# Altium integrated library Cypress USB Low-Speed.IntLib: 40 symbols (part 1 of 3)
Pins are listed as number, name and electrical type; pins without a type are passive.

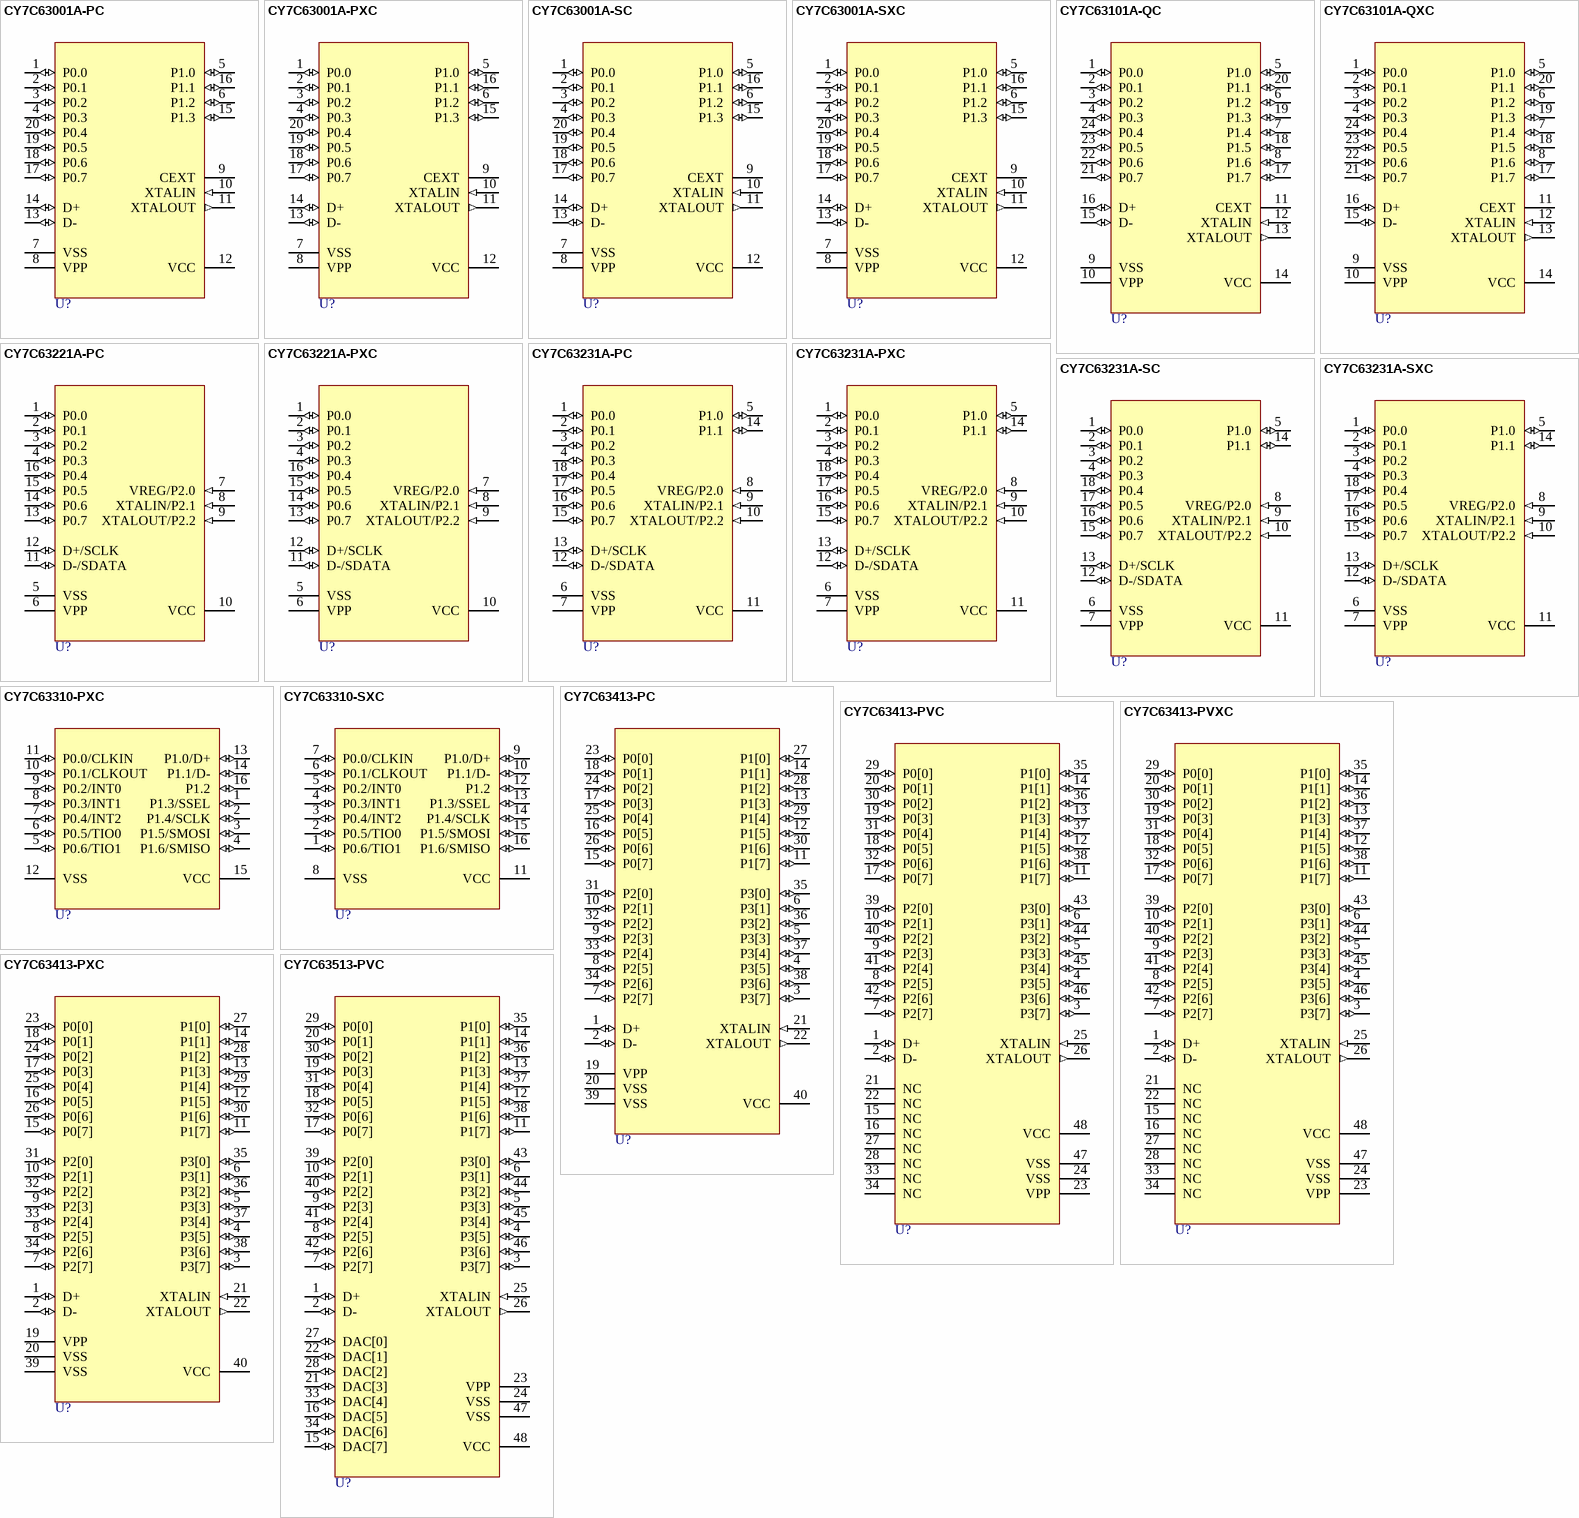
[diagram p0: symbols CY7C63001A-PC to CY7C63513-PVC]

## CY7C63001A-PC
designator U?
Low-Speed USB Peripheral Controller, 4KB EPROM, 20-Pin PDIP, Commercial Grade
footprint P5 (DIP, 20-Leads, Row Spacing 7.62mm, Pitch 2.54mm, Body 25.53x6.6mm)
pins: 1 P0.0 (io) "Port 0 bit 0", 2 P0.1 (io) "Port 0 bit 1", 3 P0.2 (io) "Port 0 bit 2", 4 P0.3 (io) "Port 0 bit 3", 5 P1.0 (io) "Port 1 bit 0", 6 P1.2 (io) "Port 1 bit 2", 7 VSS (power) "Ground", 8 VPP (power) "Programming voltage supply, tie to ground during normal operation", 9 CEXT "Connects to external R/C timing circuit for optional ‘suspend’ wakeup", 10 XTALIN (in) "Ceramic resonator", 11 XTALOUT (out) "Ceramic resonator out", 12 VCC (power) "Voltage supply", 13 D- (io) "USB data-", 14 D+ (io) "USB data+", 15 P1.3 (io) "Port 1 bit 3", 16 P1.1 (io) "Port 1 bit 1", 17 P0.7 (io) "Port 0 bit 7", 18 P0.6 (io) "Port 0 bit 6", 19 P0.5 (io) "Port 0 bit 5", 20 P0.4 (io) "Port 0 bit 4"

## CY7C63001A-PXC
designator U?
Low-Speed USB Peripheral Controller, 4KB EPROM, 20-Pin PDIP, Commercial Grade, Pb-free
footprint P5 (DIP, 20-Leads, Row Spacing 7.62mm, Pitch 2.54mm, Body 25.53x6.6mm)
pins: 1 P0.0 (io) "Port 0 bit 0", 2 P0.1 (io) "Port 0 bit 1", 3 P0.2 (io) "Port 0 bit 2", 4 P0.3 (io) "Port 0 bit 3", 5 P1.0 (io) "Port 1 bit 0", 6 P1.2 (io) "Port 1 bit 2", 7 VSS (power) "Ground", 8 VPP (power) "Programming voltage supply, tie to ground during normal operation", 9 CEXT "Connects to external R/C timing circuit for optional ‘suspend’ wakeup", 10 XTALIN (in) "Ceramic resonator", 11 XTALOUT (out) "Ceramic resonator out", 12 VCC (power) "Voltage supply", 13 D- (io) "USB data-", 14 D+ (io) "USB data+", 15 P1.3 (io) "Port 1 bit 3", 16 P1.1 (io) "Port 1 bit 1", 17 P0.7 (io) "Port 0 bit 7", 18 P0.6 (io) "Port 0 bit 6", 19 P0.5 (io) "Port 0 bit 5", 20 P0.4 (io) "Port 0 bit 4"

## CY7C63001A-SC
designator U?
Low-Speed USB Peripheral Controller, 4KB EPROM, 20-Pin SOIC, Commercial Grade
footprint S5_N (SOIC, 20-Leads, Body 12.8x7.5mm, Pitch 1.27mm, IPC Medium Density)
footprint S5_L (SOIC, 20-Leads, Body 12.8x7.5mm, Pitch 1.27mm, IPC High Density)
footprint S5_M (SOIC, 20-Leads, Body 12.8x7.5mm, Pitch 1.27mm, IPC Low Density)
pins: 1 P0.0 (io) "Port 0 bit 0", 2 P0.1 (io) "Port 0 bit 1", 3 P0.2 (io) "Port 0 bit 2", 4 P0.3 (io) "Port 0 bit 3", 5 P1.0 (io) "Port 1 bit 0", 6 P1.2 (io) "Port 1 bit 2", 7 VSS (power) "Ground", 8 VPP (power) "Programming voltage supply, tie to ground during normal operation", 9 CEXT "Connects to external R/C timing circuit for optional ‘suspend’ wakeup", 10 XTALIN (in) "Ceramic resonator", 11 XTALOUT (out) "Ceramic resonator out", 12 VCC (power) "Voltage supply", 13 D- (io) "USB data-", 14 D+ (io) "USB data+", 15 P1.3 (io) "Port 1 bit 3", 16 P1.1 (io) "Port 1 bit 1", 17 P0.7 (io) "Port 0 bit 7", 18 P0.6 (io) "Port 0 bit 6", 19 P0.5 (io) "Port 0 bit 5", 20 P0.4 (io) "Port 0 bit 4"

## CY7C63001A-SXC
designator U?
Low-Speed USB Peripheral Controller, 4KB EPROM, 20-Pin SOIC, Commercial Grade, Pb-free
footprint S5_N (SOIC, 20-Leads, Body 12.8x7.5mm, Pitch 1.27mm, IPC Medium Density)
footprint S5_L (SOIC, 20-Leads, Body 12.8x7.5mm, Pitch 1.27mm, IPC High Density)
footprint S5_M (SOIC, 20-Leads, Body 12.8x7.5mm, Pitch 1.27mm, IPC Low Density)
pins: 1 P0.0 (io) "Port 0 bit 0", 2 P0.1 (io) "Port 0 bit 1", 3 P0.2 (io) "Port 0 bit 2", 4 P0.3 (io) "Port 0 bit 3", 5 P1.0 (io) "Port 1 bit 0", 6 P1.2 (io) "Port 1 bit 2", 7 VSS (power) "Ground", 8 VPP (power) "Programming voltage supply, tie to ground during normal operation", 9 CEXT "Connects to external R/C timing circuit for optional ‘suspend’ wakeup", 10 XTALIN (in) "Ceramic resonator", 11 XTALOUT (out) "Ceramic resonator out", 12 VCC (power) "Voltage supply", 13 D- (io) "USB data-", 14 D+ (io) "USB data+", 15 P1.3 (io) "Port 1 bit 3", 16 P1.1 (io) "Port 1 bit 1", 17 P0.7 (io) "Port 0 bit 7", 18 P0.6 (io) "Port 0 bit 6", 19 P0.5 (io) "Port 0 bit 5", 20 P0.4 (io) "Port 0 bit 4"

## CY7C63101A-QC
designator U?
Low-Speed USB Peripheral Controller, 4KB EPROM, 24-Pin QSOP, Commercial Grade
footprint Q13_N (SOP, 24-Leads, Body 8.6x3.9mm, Pitch 0.635mm, IPC Medium Density)
footprint Q13_L (SOP, 24-Leads, Body 8.6x3.9mm, Pitch 0.635mm, IPC High Density)
footprint Q13_M (SOP, 24-Leads, Body 8.6x3.9mm, Pitch 0.635mm, IPC Low Density)
pins: 1 P0.0 (io) "Port 0 bit 0", 2 P0.1 (io) "Port 0 bit 1", 3 P0.2 (io) "Port 0 bit 2", 4 P0.3 (io) "Port 0 bit 3", 5 P1.0 (io) "Port 1 bit 0", 6 P1.2 (io) "Port 1 bit 2", 7 P1.4 (io) "Port 1 bit 4", 8 P1.6 (io) "Port 1 bit 6", 9 VSS (power) "Ground", 10 VPP (power) "Programming voltage supply, tie to ground during normal operation", 11 CEXT "Connects to external R/C timing circuit for optional ‘suspend’ wakeup", 12 XTALIN (in) "Ceramic resonator", 13 XTALOUT (out) "Ceramic resonator out", 14 VCC (power) "Voltage supply", 15 D- (io) "USB data-", 16 D+ (io) "USB data+", 17 P1.7 (io) "Port 1 bit 7", 18 P1.5 (io) "Port 1 bit 5", 19 P1.3 (io) "Port 1 bit 3", 20 P1.1 (io) "Port 1 bit 1", 21 P0.7 (io) "Port 0 bit 7", 22 P0.6 (io) "Port 0 bit 6", 23 P0.5 (io) "Port 0 bit 5", 24 P0.4 (io) "Port 0 bit 4"

## CY7C63101A-QXC
designator U?
Low-Speed USB Peripheral Controller, 4KB EPROM, 24-Pin QSOP, Commercial Grade, Pb-free
footprint Q13_N (SOP, 24-Leads, Body 8.6x3.9mm, Pitch 0.635mm, IPC Medium Density)
footprint Q13_L (SOP, 24-Leads, Body 8.6x3.9mm, Pitch 0.635mm, IPC High Density)
footprint Q13_M (SOP, 24-Leads, Body 8.6x3.9mm, Pitch 0.635mm, IPC Low Density)
pins: 1 P0.0 (io) "Port 0 bit 0", 2 P0.1 (io) "Port 0 bit 1", 3 P0.2 (io) "Port 0 bit 2", 4 P0.3 (io) "Port 0 bit 3", 5 P1.0 (io) "Port 1 bit 0", 6 P1.2 (io) "Port 1 bit 2", 7 P1.4 (io) "Port 1 bit 4", 8 P1.6 (io) "Port 1 bit 6", 9 VSS (power) "Ground", 10 VPP (power) "Programming voltage supply, tie to ground during normal operation", 11 CEXT "Connects to external R/C timing circuit for optional ‘suspend’ wakeup", 12 XTALIN (in) "Ceramic resonator", 13 XTALOUT (out) "Ceramic resonator out", 14 VCC (power) "Voltage supply", 15 D- (io) "USB data-", 16 D+ (io) "USB data+", 17 P1.7 (io) "Port 1 bit 7", 18 P1.5 (io) "Port 1 bit 5", 19 P1.3 (io) "Port 1 bit 3", 20 P1.1 (io) "Port 1 bit 1", 21 P0.7 (io) "Port 0 bit 7", 22 P0.6 (io) "Port 0 bit 6", 23 P0.5 (io) "Port 0 bit 5", 24 P0.4 (io) "Port 0 bit 4"

## CY7C63221A-PC
designator U?
enCoRe, Low-Speed USB Peripheral Controller, 3KB EPROM, 16-Pin PDIP, Commercial Grade
footprint P1 (DIP, 16-Leads, Row Spacing 7.62mm, Pitch 2.54mm, Body 19.18x6.35mm)
pins: 1 P0.0 (io) "GPIO Port 0 capable of sinking up to 50 mA/pin, or sinking controlled low or high programmable current. Can also source 2 mA current, provide a resistive pull-up, or serve as a high-impedance input.", 2 P0.1 (io) "GPIO Port 0 capable of sinking up to 50 mA/pin, or sinking controlled low or high programmable current. Can also source 2 mA current, provide a resistive pull-up, or serve as a high-impedance input.", 3 P0.2 (io) "GPIO Port 0 capable of sinking up to 50 mA/pin, or sinking controlled low or high programmable current. Can also source 2 mA current, provide a resistive pull-up, or serve as a high-impedance input.", 4 P0.3 (io) "GPIO Port 0 capable of sinking up to 50 mA/pin, or sinking controlled low or high programmable current. Can also source 2 mA current, provide a resistive pull-up, or serve as a high-impedance input.", 5 VSS (power) "Ground", 6 VPP (power) "Programming voltage supply, ground for normal operation", 7 VREG/P2.0 (in) "Voltage supply for 1.3-k? USB pull-up resistor (3.3V nominal). Also serves as P2.0 input.", 8 XTALIN/P2.1 (in) "6-MHz ceramic resonator or external clock input, or P2.1 input", 9 XTALOUT/P2.2 (in) "6-MHz ceramic resonator return pin or internal oscillator output, or P2.2 input", 10 VCC (power) "Voltage supply", 11 D-/SDATA (io) "USB differential data line or PS/2 data signal", 12 D+/SCLK (io) "USB differential data line or PS/2 clock signal", 13 P0.7 (io) "GPIO Port 0 capable of sinking up to 50 mA/pin, or sinking controlled low or high programmable current. Can also source 2 mA current, provide a resistive pull-up, or serve as a high-impedance input.", 14 P0.6 (io) "GPIO Port 0 capable of sinking up to 50 mA/pin, or sinking controlled low or high programmable current. Can also source 2 mA current, provide a resistive pull-up, or serve as a high-impedance input.", 15 P0.5 (io) "GPIO Port 0 capable of sinking up to 50 mA/pin, or sinking controlled low or high programmable current. Can also source 2 mA current, provide a resistive pull-up, or serve as a high-impedance input.", 16 P0.4 (io) "GPIO Port 0 capable of sinking up to 50 mA/pin, or sinking controlled low or high programmable current. Can also source 2 mA current, provide a resistive pull-up, or serve as a high-impedance input."

## CY7C63221A-PXC
designator U?
enCoRe, Low-Speed USB Peripheral Controller, 3KB EPROM, 16-Pin PDIP, Commercial Grade, Pb-free
footprint P1 (DIP, 16-Leads, Row Spacing 7.62mm, Pitch 2.54mm, Body 19.18x6.35mm)
pins: 1 P0.0 (io) "GPIO Port 0 capable of sinking up to 50 mA/pin, or sinking controlled low or high programmable current. Can also source 2 mA current, provide a resistive pull-up, or serve as a high-impedance input.", 2 P0.1 (io) "GPIO Port 0 capable of sinking up to 50 mA/pin, or sinking controlled low or high programmable current. Can also source 2 mA current, provide a resistive pull-up, or serve as a high-impedance input.", 3 P0.2 (io) "GPIO Port 0 capable of sinking up to 50 mA/pin, or sinking controlled low or high programmable current. Can also source 2 mA current, provide a resistive pull-up, or serve as a high-impedance input.", 4 P0.3 (io) "GPIO Port 0 capable of sinking up to 50 mA/pin, or sinking controlled low or high programmable current. Can also source 2 mA current, provide a resistive pull-up, or serve as a high-impedance input.", 5 VSS (power) "Ground", 6 VPP (power) "Programming voltage supply, ground for normal operation", 7 VREG/P2.0 (in) "Voltage supply for 1.3-k? USB pull-up resistor (3.3V nominal). Also serves as P2.0 input.", 8 XTALIN/P2.1 (in) "6-MHz ceramic resonator or external clock input, or P2.1 input", 9 XTALOUT/P2.2 (in) "6-MHz ceramic resonator return pin or internal oscillator output, or P2.2 input", 10 VCC (power) "Voltage supply", 11 D-/SDATA (io) "USB differential data line or PS/2 data signal", 12 D+/SCLK (io) "USB differential data line or PS/2 clock signal", 13 P0.7 (io) "GPIO Port 0 capable of sinking up to 50 mA/pin, or sinking controlled low or high programmable current. Can also source 2 mA current, provide a resistive pull-up, or serve as a high-impedance input.", 14 P0.6 (io) "GPIO Port 0 capable of sinking up to 50 mA/pin, or sinking controlled low or high programmable current. Can also source 2 mA current, provide a resistive pull-up, or serve as a high-impedance input.", 15 P0.5 (io) "GPIO Port 0 capable of sinking up to 50 mA/pin, or sinking controlled low or high programmable current. Can also source 2 mA current, provide a resistive pull-up, or serve as a high-impedance input.", 16 P0.4 (io) "GPIO Port 0 capable of sinking up to 50 mA/pin, or sinking controlled low or high programmable current. Can also source 2 mA current, provide a resistive pull-up, or serve as a high-impedance input."

## CY7C63231A-PC
designator U?
enCoRe, Low-Speed USB Peripheral Controller, 3KB EPROM, 18-Pin PDIP, Commercial Grade
footprint P3 (DIP, 18-Leads, Row Spacing 7.62mm, Pitch 2.54mm, Body 22.73x6.48mm)
pins: 1 P0.0 (io) "GPIO Port 0 capable of sinking up to 50 mA/pin, or sinking controlled low or high programmable current. Can also source 2 mA current, provide a resistive pull-up, or serve as a high-impedance input.", 2 P0.1 (io) "GPIO Port 0 capable of sinking up to 50 mA/pin, or sinking controlled low or high programmable current. Can also source 2 mA current, provide a resistive pull-up, or serve as a high-impedance input.", 3 P0.2 (io) "GPIO Port 0 capable of sinking up to 50 mA/pin, or sinking controlled low or high programmable current. Can also source 2 mA current, provide a resistive pull-up, or serve as a high-impedance input.", 4 P0.3 (io) "GPIO Port 0 capable of sinking up to 50 mA/pin, or sinking controlled low or high programmable current. Can also source 2 mA current, provide a resistive pull-up, or serve as a high-impedance input.", 5 P1.0 (io) "IO Port 1 capable of sinking up to 50 mA/pin, or sinking controlled low or high programmable current. Can also source 2 mA current, provide a resistive pull-up, or serve as a high-impedance input.", 6 VSS (power) "Ground", 7 VPP (power) "Programming voltage supply, ground for normal operation", 8 VREG/P2.0 (in) "Voltage supply for 1.3-k? USB pull-up resistor (3.3V nominal). Also serves as P2.0 input.", 9 XTALIN/P2.1 (in) "6-MHz ceramic resonator or external clock input, or P2.1 input", 10 XTALOUT/P2.2 (in) "6-MHz ceramic resonator return pin or internal oscillator output, or P2.2 input", 11 VCC (power) "Voltage supply", 12 D-/SDATA (io) "USB differential data line or PS/2 data signal", 13 D+/SCLK (io) "USB differential data line or PS/2 clock signal", 14 P1.1 (io) "IO Port 1 capable of sinking up to 50 mA/pin, or sinking controlled low or high programmable current. Can also source 2 mA current, provide a resistive pull-up, or serve as a high-impedance input.", 15 P0.7 (io) "GPIO Port 0 capable of sinking up to 50 mA/pin, or sinking controlled low or high programmable current. Can also source 2 mA current, provide a resistive pull-up, or serve as a high-impedance input.", 16 P0.6 (io) "GPIO Port 0 capable of sinking up to 50 mA/pin, or sinking controlled low or high programmable current. Can also source 2 mA current, provide a resistive pull-up, or serve as a high-impedance input.", 17 P0.5 (io) "GPIO Port 0 capable of sinking up to 50 mA/pin, or sinking controlled low or high programmable current. Can also source 2 mA current, provide a resistive pull-up, or serve as a high-impedance input.", 18 P0.4 (io) "GPIO Port 0 capable of sinking up to 50 mA/pin, or sinking controlled low or high programmable current. Can also source 2 mA current, provide a resistive pull-up, or serve as a high-impedance input."

## CY7C63231A-PXC
designator U?
enCoRe, Low-Speed USB Peripheral Controller, 3KB EPROM, 18-Pin PDIP, Commercial Grade, Pb-free
footprint P3 (DIP, 18-Leads, Row Spacing 7.62mm, Pitch 2.54mm, Body 22.73x6.48mm)
pins: 1 P0.0 (io) "GPIO Port 0 capable of sinking up to 50 mA/pin, or sinking controlled low or high programmable current. Can also source 2 mA current, provide a resistive pull-up, or serve as a high-impedance input.", 2 P0.1 (io) "GPIO Port 0 capable of sinking up to 50 mA/pin, or sinking controlled low or high programmable current. Can also source 2 mA current, provide a resistive pull-up, or serve as a high-impedance input.", 3 P0.2 (io) "GPIO Port 0 capable of sinking up to 50 mA/pin, or sinking controlled low or high programmable current. Can also source 2 mA current, provide a resistive pull-up, or serve as a high-impedance input.", 4 P0.3 (io) "GPIO Port 0 capable of sinking up to 50 mA/pin, or sinking controlled low or high programmable current. Can also source 2 mA current, provide a resistive pull-up, or serve as a high-impedance input.", 5 P1.0 (io) "IO Port 1 capable of sinking up to 50 mA/pin, or sinking controlled low or high programmable current. Can also source 2 mA current, provide a resistive pull-up, or serve as a high-impedance input.", 6 VSS (power) "Ground", 7 VPP (power) "Programming voltage supply, ground for normal operation", 8 VREG/P2.0 (in) "Voltage supply for 1.3-k? USB pull-up resistor (3.3V nominal). Also serves as P2.0 input.", 9 XTALIN/P2.1 (in) "6-MHz ceramic resonator or external clock input, or P2.1 input", 10 XTALOUT/P2.2 (in) "6-MHz ceramic resonator return pin or internal oscillator output, or P2.2 input", 11 VCC (power) "Voltage supply", 12 D-/SDATA (io) "USB differential data line or PS/2 data signal", 13 D+/SCLK (io) "USB differential data line or PS/2 clock signal", 14 P1.1 (io) "IO Port 1 capable of sinking up to 50 mA/pin, or sinking controlled low or high programmable current. Can also source 2 mA current, provide a resistive pull-up, or serve as a high-impedance input.", 15 P0.7 (io) "GPIO Port 0 capable of sinking up to 50 mA/pin, or sinking controlled low or high programmable current. Can also source 2 mA current, provide a resistive pull-up, or serve as a high-impedance input.", 16 P0.6 (io) "GPIO Port 0 capable of sinking up to 50 mA/pin, or sinking controlled low or high programmable current. Can also source 2 mA current, provide a resistive pull-up, or serve as a high-impedance input.", 17 P0.5 (io) "GPIO Port 0 capable of sinking up to 50 mA/pin, or sinking controlled low or high programmable current. Can also source 2 mA current, provide a resistive pull-up, or serve as a high-impedance input.", 18 P0.4 (io) "GPIO Port 0 capable of sinking up to 50 mA/pin, or sinking controlled low or high programmable current. Can also source 2 mA current, provide a resistive pull-up, or serve as a high-impedance input."

## CY7C63231A-SC
designator U?
enCoRe, Low-Speed USB Peripheral Controller, 3KB EPROM, 18-Pin SOIC, Commercial Grade
footprint S1_N (SOIC, 18-Leads, Body 11.6x7.5mm, Pitch 1.27mm, IPC Medium Density)
footprint S1_L (SOIC, 18-Leads, Body 11.6x7.5mm, Pitch 1.27mm, IPC High Density)
footprint S1_M (SOIC, 18-Leads, Body 11.6x7.5mm, Pitch 1.27mm, IPC Low Density)
pins: 1 P0.0 (io) "GPIO Port 0 capable of sinking up to 50 mA/pin, or sinking controlled low or high programmable current. Can also source 2 mA current, provide a resistive pull-up, or serve as a high-impedance input.", 2 P0.1 (io) "GPIO Port 0 capable of sinking up to 50 mA/pin, or sinking controlled low or high programmable current. Can also source 2 mA current, provide a resistive pull-up, or serve as a high-impedance input.", 3 P0.2 (io) "GPIO Port 0 capable of sinking up to 50 mA/pin, or sinking controlled low or high programmable current. Can also source 2 mA current, provide a resistive pull-up, or serve as a high-impedance input.", 4 P0.3 (io) "GPIO Port 0 capable of sinking up to 50 mA/pin, or sinking controlled low or high programmable current. Can also source 2 mA current, provide a resistive pull-up, or serve as a high-impedance input.", 5 P1.0 (io) "IO Port 1 capable of sinking up to 50 mA/pin, or sinking controlled low or high programmable current. Can also source 2 mA current, provide a resistive pull-up, or serve as a high-impedance input.", 6 VSS (power) "Ground", 7 VPP (power) "Programming voltage supply, ground for normal operation", 8 VREG/P2.0 (in) "Voltage supply for 1.3-k? USB pull-up resistor (3.3V nominal). Also serves as P2.0 input.", 9 XTALIN/P2.1 (in) "6-MHz ceramic resonator or external clock input, or P2.1 input", 10 XTALOUT/P2.2 (in) "6-MHz ceramic resonator return pin or internal oscillator output, or P2.2 input", 11 VCC (power) "Voltage supply", 12 D-/SDATA (io) "USB differential data line or PS/2 data signal", 13 D+/SCLK (io) "USB differential data line or PS/2 clock signal", 14 P1.1 (io) "IO Port 1 capable of sinking up to 50 mA/pin, or sinking controlled low or high programmable current. Can also source 2 mA current, provide a resistive pull-up, or serve as a high-impedance input.", 15 P0.7 (io) "GPIO Port 0 capable of sinking up to 50 mA/pin, or sinking controlled low or high programmable current. Can also source 2 mA current, provide a resistive pull-up, or serve as a high-impedance input.", 16 P0.6 (io) "GPIO Port 0 capable of sinking up to 50 mA/pin, or sinking controlled low or high programmable current. Can also source 2 mA current, provide a resistive pull-up, or serve as a high-impedance input.", 17 P0.5 (io) "GPIO Port 0 capable of sinking up to 50 mA/pin, or sinking controlled low or high programmable current. Can also source 2 mA current, provide a resistive pull-up, or serve as a high-impedance input.", 18 P0.4 (io) "GPIO Port 0 capable of sinking up to 50 mA/pin, or sinking controlled low or high programmable current. Can also source 2 mA current, provide a resistive pull-up, or serve as a high-impedance input."

## CY7C63231A-SXC
designator U?
enCoRe, Low-Speed USB Peripheral Controller, 3KB EPROM, 18-Pin SOIC, Commercial Grade, Pb-free
footprint S1_N (SOIC, 18-Leads, Body 11.6x7.5mm, Pitch 1.27mm, IPC Medium Density)
footprint S1_L (SOIC, 18-Leads, Body 11.6x7.5mm, Pitch 1.27mm, IPC High Density)
footprint S1_M (SOIC, 18-Leads, Body 11.6x7.5mm, Pitch 1.27mm, IPC Low Density)
pins: 1 P0.0 (io) "GPIO Port 0 capable of sinking up to 50 mA/pin, or sinking controlled low or high programmable current. Can also source 2 mA current, provide a resistive pull-up, or serve as a high-impedance input.", 2 P0.1 (io) "GPIO Port 0 capable of sinking up to 50 mA/pin, or sinking controlled low or high programmable current. Can also source 2 mA current, provide a resistive pull-up, or serve as a high-impedance input.", 3 P0.2 (io) "GPIO Port 0 capable of sinking up to 50 mA/pin, or sinking controlled low or high programmable current. Can also source 2 mA current, provide a resistive pull-up, or serve as a high-impedance input.", 4 P0.3 (io) "GPIO Port 0 capable of sinking up to 50 mA/pin, or sinking controlled low or high programmable current. Can also source 2 mA current, provide a resistive pull-up, or serve as a high-impedance input.", 5 P1.0 (io) "IO Port 1 capable of sinking up to 50 mA/pin, or sinking controlled low or high programmable current. Can also source 2 mA current, provide a resistive pull-up, or serve as a high-impedance input.", 6 VSS (power) "Ground", 7 VPP (power) "Programming voltage supply, ground for normal operation", 8 VREG/P2.0 (in) "Voltage supply for 1.3-k? USB pull-up resistor (3.3V nominal). Also serves as P2.0 input.", 9 XTALIN/P2.1 (in) "6-MHz ceramic resonator or external clock input, or P2.1 input", 10 XTALOUT/P2.2 (in) "6-MHz ceramic resonator return pin or internal oscillator output, or P2.2 input", 11 VCC (power) "Voltage supply", 12 D-/SDATA (io) "USB differential data line or PS/2 data signal", 13 D+/SCLK (io) "USB differential data line or PS/2 clock signal", 14 P1.1 (io) "IO Port 1 capable of sinking up to 50 mA/pin, or sinking controlled low or high programmable current. Can also source 2 mA current, provide a resistive pull-up, or serve as a high-impedance input.", 15 P0.7 (io) "GPIO Port 0 capable of sinking up to 50 mA/pin, or sinking controlled low or high programmable current. Can also source 2 mA current, provide a resistive pull-up, or serve as a high-impedance input.", 16 P0.6 (io) "GPIO Port 0 capable of sinking up to 50 mA/pin, or sinking controlled low or high programmable current. Can also source 2 mA current, provide a resistive pull-up, or serve as a high-impedance input.", 17 P0.5 (io) "GPIO Port 0 capable of sinking up to 50 mA/pin, or sinking controlled low or high programmable current. Can also source 2 mA current, provide a resistive pull-up, or serve as a high-impedance input.", 18 P0.4 (io) "GPIO Port 0 capable of sinking up to 50 mA/pin, or sinking controlled low or high programmable current. Can also source 2 mA current, provide a resistive pull-up, or serve as a high-impedance input."

## CY7C63310-PXC
designator U?
enCoRe II, Low-Speed USB Peripheral Controller, 3KB FLASH, 16-Pin PDIP, Commercial Grade, Pb-free
footprint P1 (DIP, 16-Leads, Row Spacing 7.62mm, Pitch 2.54mm, Body 19.18x6.35mm)
pins: 1 P1.3/SSEL (io) "GPIO Port 1 bit 3 - Configured individually. Alternate function is SSEL signal of the SPI bus TTL voltage thresholds", 2 P1.4/SCLK (io) "GPIO Port 1 bit 4 - Configured individually. Alternate function is SCLK signal of the SPI bus TTL voltage thresholds", 3 P1.5/SMOSI (io) "GPIO Port 1 bit 5 - Configured individually. Alternate function is SMOSI signal of the SPI bus TTL voltage thresholds", 4 P1.6/SMISO (io) "GPIO Port 1 bit 6 - Configured individually. Alternate function is SMISO signal of the SPI bus TTL voltage thresholds", 5 P0.6/TIO1 (io) "GPIO port 0 bit 6 - Configured individually Alternate function Timer capture inputs or Timer output TIO1", 6 P0.5/TIO0 (io) "GPIO port 0 bit 5 - Configured individually Alternate function Timer capture inputs or Timer output TIO0", 7 P0.4/INT2 (io) "GPIO port 0 bit 4 - Configured individually Optional rising edge interrupt INT2", 8 P0.3/INT1 (io) "GPIO port 0 bit 3 - Configured individually Optional rising edge interrupt INT1", 9 P0.2/INT0 (io) "GPIO port 0 bit 2 - Configured individually Optional rising edge interrupt INT0", 10 P0.1/CLKOUT (io) "GPIO Port 0 bit 1 - Configured individually. Oscillator output when configured as Clock Out.", 11 P0.0/CLKIN (io) "GPIO Port 0 bit 0 - Configured individually. Oscillator input when configured as Clock In.", 12 VSS (power) "Ground", 13 P1.0/D+ (io) "GPIO Port 1 bit 0 / USB D+", 14 P1.1/D- (io) "GPIO Port 1 bit 1 / USB D-", 15 VCC (power) "Power", 16 P1.2 (io) "GPIO Port 1 bit 2 - Configured individually."

## CY7C63310-SXC
designator U?
enCoRe II, Low-Speed USB Peripheral Controller, 3KB FLASH, 16-Pin SOIC, Commercial Grade, Pb-free
footprint S16.15_N (SOIC, 16-Leads, Body 9.9x3.9mm, Pitch 1.27mm, IPC Medium Density)
footprint S16.15_L (SOIC, 16-Leads, Body 9.9x3.9mm, Pitch 1.27mm, IPC High Density)
footprint S16.15_M (SOIC, 16-Leads, Body 9.9x3.9mm, Pitch 1.27mm, IPC Low Density)
pins: 1 P0.6/TIO1 (io) "GPIO port 0 bit 6 - Configured individually Alternate function Timer capture inputs or Timer output TIO1", 2 P0.5/TIO0 (io) "GPIO port 0 bit 5 - Configured individually Alternate function Timer capture inputs or Timer output TIO0", 3 P0.4/INT2 (io) "GPIO port 0 bit 4 - Configured individually Optional rising edge interrupt INT2", 4 P0.3/INT1 (io) "GPIO port 0 bit 3 - Configured individually Optional rising edge interrupt INT1", 5 P0.2/INT0 (io) "GPIO port 0 bit 2 - Configured individually Optional rising edge interrupt INT0", 6 P0.1/CLKOUT (io) "GPIO Port 0 bit 1 - Configured individually. Oscillator output when configured as Clock Out.", 7 P0.0/CLKIN (io) "GPIO Port 0 bit 0 - Configured individually. Oscillator input when configured as Clock In.", 8 VSS (power) "Ground", 9 P1.0/D+ (io) "GPIO Port 1 bit 0 / USB D+", 10 P1.1/D- (io) "GPIO Port 1 bit 1 / USB D-", 11 VCC (power) "Power", 12 P1.2 (io) "GPIO Port 1 bit 2 - Configured individually.", 13 P1.3/SSEL (io) "GPIO Port 1 bit 3 - Configured individually. Alternate function is SSEL signal of the SPI bus TTL voltage thresholds", 14 P1.4/SCLK (io) "GPIO Port 1 bit 4 - Configured individually. Alternate function is SCLK signal of the SPI bus TTL voltage thresholds", 15 P1.5/SMOSI (io) "GPIO Port 1 bit 5 - Configured individually. Alternate function is SMOSI signal of the SPI bus TTL voltage thresholds", 16 P1.6/SMISO (io) "GPIO Port 1 bit 6 - Configured individually. Alternate function is SMISO signal of the SPI bus TTL voltage thresholds"

## CY7C63413-PC
designator U?
Low-Speed USB Microcontroller, 8KB EPROM, 40-Pin PDIP, Commercial Grade
footprint P17 (DIP, 40-Leads, Row Spacing 15.24mm, Pitch 2.54mm, Body 52.2x13.72mm)
pins: 1 D+ (io) "USB differential data; PS/2 clock and data signals", 2 D- (io) "USB differential data; PS/2 clock and data signals", 3 P3[7] (io) "GPIO Port 3 - Bit 7. Capable of sinking 12 mA (typical).", 4 P3[5] (io) "GPIO Port 3 - Bit 5. Capable of sinking 12 mA (typical).", 5 P3[3] (io) "GPIO Port 3 - Bit 3. Capable of sinking 12 mA (typical).", 6 P3[1] (io) "GPIO Port 3 - Bit 1. Capable of sinking 12 mA (typical).", 7 P2[7] (io) "GPIO Port 2 - Bit 7. Capable of sinking 7 mA (typical).", 8 P2[5] (io) "GPIO Port 2 - Bit 5. Capable of sinking 7 mA (typical).", 9 P2[3] (io) "GPIO Port 2 - Bit 3. Capable of sinking 7 mA (typical).", 10 P2[1] (io) "GPIO Port 2 - Bit 1. Capable of sinking 7 mA (typical).", 11 P1[7] (io) "GPIO Port 1 - Bit 7. Capable of sinking 7 mA (typical).", 12 P1[5] (io) "GPIO Port 1 - Bit 5. Capable of sinking 7 mA (typical).", 13 P1[3] (io) "GPIO Port 1 - Bit 3. Capable of sinking 7 mA (typical).", 14 P1[1] (io) "GPIO Port 1 - Bit 1. Capable of sinking 7 mA (typical).", 15 P0[7] (io) "GPIO port 0 - Bit 7. Capable of sinking 7 mA (typical)", 16 P0[5] (io) "GPIO port 0 - Bit 5. Capable of sinking 7 mA (typical)", 17 P0[3] (io) "GPIO port 0 - Bit 3. Capable of sinking 7 mA (typical)", 18 P0[1] (io) "GPIO port 0 - Bit 1. Capable of sinking 7 mA (typical)", 19 VPP (power) "Programming voltage supply, ground during operation", 20 VSS (power) "Ground", 21 XTALIN (in) "6-MHz ceramic resonator or external clock input", 22 XTALOUT (out) "6-MHz ceramic resonator", 23 P0[0] (io) "GPIO port 0 - Bit 0. Capable of sinking 7 mA (typical)", 24 P0[2] (io) "GPIO port 0 - Bit 2. Capable of sinking 7 mA (typical)", 25 P0[4] (io) "GPIO port 0 - Bit 4. Capable of sinking 7 mA (typical)", 26 P0[6] (io) "GPIO port 0 - Bit 6. Capable of sinking 7 mA (typical)", 27 P1[0] (io) "GPIO Port 1 - Bit 0. Capable of sinking 7 mA (typical).", 28 P1[2] (io) "GPIO Port 1 - Bit 2. Capable of sinking 7 mA (typical).", 29 P1[4] (io) "GPIO Port 1 - Bit 4. Capable of sinking 7 mA (typical).", 30 P1[6] (io) "GPIO Port 1 - Bit 6. Capable of sinking 7 mA (typical).", 31 P2[0] (io) "GPIO Port 2 - Bit 0. Capable of sinking 7 mA (typical).", 32 P2[2] (io) "GPIO Port 2 - Bit 2. Capable of sinking 7 mA (typical).", 33 P2[4] (io) "GPIO Port 2 - Bit 4. Capable of sinking 7 mA (typical).", 34 P2[6] (io) "GPIO Port 2 - Bit 6. Capable of sinking 7 mA (typical).", 35 P3[0] (io) "GPIO Port 3 - Bit 0. Capable of sinking 12 mA (typical).", 36 P3[2] (io) "GPIO Port 3 - Bit 2. Capable of sinking 12 mA (typical).", 37 P3[4] (io) "GPIO Port 3 - Bit 4. Capable of sinking 12 mA (typical).", 38 P3[6] (io) "GPIO Port 3 - Bit 6. Capable of sinking 12 mA (typical).", 39 VSS (power) "Ground", 40 VCC (power) "Voltage supply"

## CY7C63413-PVC
designator U?
Low-Speed USB Microcontroller, 8KB EPROM, 48-Pin SSOP, Commercial Grade
footprint O48_N (SOP, 48-Leads, Body 15.9x7.5mm, Pitch 0.635mm, IPC Medium Density)
footprint O48_L (SOP, 48-Leads, Body 15.9x7.5mm, Pitch 0.635mm, IPC High Density)
footprint O48_M (SOP, 48-Leads, Body 15.9x7.5mm, Pitch 0.635mm, IPC Low Density)
pins: 1 D+ (io) "USB differential data; PS/2 clock and data signals", 2 D- (io) "USB differential data; PS/2 clock and data signals", 3 P3[7] (io) "GPIO Port 3 - Bit 7. Capable of sinking 12 mA (typical).", 4 P3[5] (io) "GPIO Port 3 - Bit 5. Capable of sinking 12 mA (typical).", 5 P3[3] (io) "GPIO Port 3 - Bit 3. Capable of sinking 12 mA (typical).", 6 P3[1] (io) "GPIO Port 3 - Bit 1. Capable of sinking 12 mA (typical).", 7 P2[7] (io) "GPIO Port 2 - Bit 7. Capable of sinking 7 mA (typical).", 8 P2[5] (io) "GPIO Port 2 - Bit 5. Capable of sinking 7 mA (typical).", 9 P2[3] (io) "GPIO Port 2 - Bit 3. Capable of sinking 7 mA (typical).", 10 P2[1] (io) "GPIO Port 2 - Bit 1. Capable of sinking 7 mA (typical).", 11 P1[7] (io) "GPIO Port 1 - Bit 7. Capable of sinking 7 mA (typical).", 12 P1[5] (io) "GPIO Port 1 - Bit 5. Capable of sinking 7 mA (typical).", 13 P1[3] (io) "GPIO Port 1 - Bit 3. Capable of sinking 7 mA (typical).", 14 P1[1] (io) "GPIO Port 1 - Bit 1. Capable of sinking 7 mA (typical).", 15 NC "No Connect.  DAC available on the CY7C63513 part.", 16 NC "No Connect.  DAC available on the CY7C63513 part.", 17 P0[7] (io) "GPIO port 0 - Bit 7. Capable of sinking 7 mA (typical)", 18 P0[5] (io) "GPIO port 0 - Bit 5. Capable of sinking 7 mA (typical)", 19 P0[3] (io) "GPIO port 0 - Bit 3. Capable of sinking 7 mA (typical)", 20 P0[1] (io) "GPIO port 0 - Bit 1. Capable of sinking 7 mA (typical)", 21 NC "No Connect.  DAC available on the CY7C63513 part.", 22 NC "No Connect.  DAC available on the CY7C63513 part.", 23 VPP (power) "Programming voltage supply, ground during operation", 24 VSS (power) "Ground", 25 XTALIN (in) "6-MHz ceramic resonator or external clock input", 26 XTALOUT (out) "6-MHz ceramic resonator", 27 NC "No Connect.  DAC available on the CY7C63513 part.", 28 NC "No Connect.  DAC available on the CY7C63513 part.", 29 P0[0] (io) "GPIO port 0 - Bit 0. Capable of sinking 7 mA (typical)", 30 P0[2] (io) "GPIO port 0 - Bit 2. Capable of sinking 7 mA (typical)", 31 P0[4] (io) "GPIO port 0 - Bit 4. Capable of sinking 7 mA (typical)", 32 P0[6] (io) "GPIO port 0 - Bit 6. Capable of sinking 7 mA (typical)", 33 NC "No Connect.  DAC available on the CY7C63513 part.", 34 NC "No Connect.  DAC available on the CY7C63513 part.", 35 P1[0] (io) "GPIO Port 1 - Bit 0. Capable of sinking 7 mA (typical).", 36 P1[2] (io) "GPIO Port 1 - Bit 2. Capable of sinking 7 mA (typical).", 37 P1[4] (io) "GPIO Port 1 - Bit 4. Capable of sinking 7 mA (typical).", 38 P1[6] (io) "GPIO Port 1 - Bit 6. Capable of sinking 7 mA (typical).", 39 P2[0] (io) "GPIO Port 2 - Bit 0. Capable of sinking 7 mA (typical).", 40 P2[2] (io) "GPIO Port 2 - Bit 2. Capable of sinking 7 mA (typical).", 41 P2[4] (io) "GPIO Port 2 - Bit 4. Capable of sinking 7 mA (typical).", 42 P2[6] (io) "GPIO Port 2 - Bit 6. Capable of sinking 7 mA (typical).", 43 P3[0] (io) "GPIO Port 3 - Bit 0. Capable of sinking 12 mA (typical).", 44 P3[2] (io) "GPIO Port 3 - Bit 2. Capable of sinking 12 mA (typical).", 45 P3[4] (io) "GPIO Port 3 - Bit 4. Capable of sinking 12 mA (typical).", 46 P3[6] (io) "GPIO Port 3 - Bit 6. Capable of sinking 12 mA (typical).", 47 VSS (power) "Ground", 48 VCC (power) "Voltage supply"

## CY7C63413-PVXC
designator U?
Low-Speed USB Microcontroller, 8KB EPROM, 48-Pin SSOP, Commercial Grade, Pb-free
footprint SP48_N (SOP, 48-Leads, Body 15.9x7.5mm, Pitch 0.635mm, IPC Medium Density)
footprint SP48_L (SOP, 48-Leads, Body 15.9x7.5mm, Pitch 0.635mm, IPC High Density)
footprint SP48_M (SOP, 48-Leads, Body 15.9x7.5mm, Pitch 0.635mm, IPC Low Density)
pins: 1 D+ (io) "USB differential data; PS/2 clock and data signals", 2 D- (io) "USB differential data; PS/2 clock and data signals", 3 P3[7] (io) "GPIO Port 3 - Bit 7. Capable of sinking 12 mA (typical).", 4 P3[5] (io) "GPIO Port 3 - Bit 5. Capable of sinking 12 mA (typical).", 5 P3[3] (io) "GPIO Port 3 - Bit 3. Capable of sinking 12 mA (typical).", 6 P3[1] (io) "GPIO Port 3 - Bit 1. Capable of sinking 12 mA (typical).", 7 P2[7] (io) "GPIO Port 2 - Bit 7. Capable of sinking 7 mA (typical).", 8 P2[5] (io) "GPIO Port 2 - Bit 5. Capable of sinking 7 mA (typical).", 9 P2[3] (io) "GPIO Port 2 - Bit 3. Capable of sinking 7 mA (typical).", 10 P2[1] (io) "GPIO Port 2 - Bit 1. Capable of sinking 7 mA (typical).", 11 P1[7] (io) "GPIO Port 1 - Bit 7. Capable of sinking 7 mA (typical).", 12 P1[5] (io) "GPIO Port 1 - Bit 5. Capable of sinking 7 mA (typical).", 13 P1[3] (io) "GPIO Port 1 - Bit 3. Capable of sinking 7 mA (typical).", 14 P1[1] (io) "GPIO Port 1 - Bit 1. Capable of sinking 7 mA (typical).", 15 NC "No Connect.  DAC available on the CY7C63513 part.", 16 NC "No Connect.  DAC available on the CY7C63513 part.", 17 P0[7] (io) "GPIO port 0 - Bit 7. Capable of sinking 7 mA (typical)", 18 P0[5] (io) "GPIO port 0 - Bit 5. Capable of sinking 7 mA (typical)", 19 P0[3] (io) "GPIO port 0 - Bit 3. Capable of sinking 7 mA (typical)", 20 P0[1] (io) "GPIO port 0 - Bit 1. Capable of sinking 7 mA (typical)", 21 NC "No Connect.  DAC available on the CY7C63513 part.", 22 NC "No Connect.  DAC available on the CY7C63513 part.", 23 VPP (power) "Programming voltage supply, ground during operation", 24 VSS (power) "Ground", 25 XTALIN (in) "6-MHz ceramic resonator or external clock input", 26 XTALOUT (out) "6-MHz ceramic resonator", 27 NC "No Connect.  DAC available on the CY7C63513 part.", 28 NC "No Connect.  DAC available on the CY7C63513 part.", 29 P0[0] (io) "GPIO port 0 - Bit 0. Capable of sinking 7 mA (typical)", 30 P0[2] (io) "GPIO port 0 - Bit 2. Capable of sinking 7 mA (typical)", 31 P0[4] (io) "GPIO port 0 - Bit 4. Capable of sinking 7 mA (typical)", 32 P0[6] (io) "GPIO port 0 - Bit 6. Capable of sinking 7 mA (typical)", 33 NC "No Connect.  DAC available on the CY7C63513 part.", 34 NC "No Connect.  DAC available on the CY7C63513 part.", 35 P1[0] (io) "GPIO Port 1 - Bit 0. Capable of sinking 7 mA (typical).", 36 P1[2] (io) "GPIO Port 1 - Bit 2. Capable of sinking 7 mA (typical).", 37 P1[4] (io) "GPIO Port 1 - Bit 4. Capable of sinking 7 mA (typical).", 38 P1[6] (io) "GPIO Port 1 - Bit 6. Capable of sinking 7 mA (typical).", 39 P2[0] (io) "GPIO Port 2 - Bit 0. Capable of sinking 7 mA (typical).", 40 P2[2] (io) "GPIO Port 2 - Bit 2. Capable of sinking 7 mA (typical).", 41 P2[4] (io) "GPIO Port 2 - Bit 4. Capable of sinking 7 mA (typical).", 42 P2[6] (io) "GPIO Port 2 - Bit 6. Capable of sinking 7 mA (typical).", 43 P3[0] (io) "GPIO Port 3 - Bit 0. Capable of sinking 12 mA (typical).", 44 P3[2] (io) "GPIO Port 3 - Bit 2. Capable of sinking 12 mA (typical).", 45 P3[4] (io) "GPIO Port 3 - Bit 4. Capable of sinking 12 mA (typical).", 46 P3[6] (io) "GPIO Port 3 - Bit 6. Capable of sinking 12 mA (typical).", 47 VSS (power) "Ground", 48 VCC (power) "Voltage supply"

## CY7C63413-PXC
designator U?
Low-Speed USB Microcontroller, 8KB EPROM, 40-Pin PDIP, Commercial Grade, Pb-free
footprint P2 (DIP, 40-Leads, Row Spacing 15.24mm, Pitch 2.54mm, Body 52.2x13.72mm)
pins: 1 D+ (io) "USB differential data; PS/2 clock and data signals", 2 D- (io) "USB differential data; PS/2 clock and data signals", 3 P3[7] (io) "GPIO Port 3 - Bit 7. Capable of sinking 12 mA (typical).", 4 P3[5] (io) "GPIO Port 3 - Bit 5. Capable of sinking 12 mA (typical).", 5 P3[3] (io) "GPIO Port 3 - Bit 3. Capable of sinking 12 mA (typical).", 6 P3[1] (io) "GPIO Port 3 - Bit 1. Capable of sinking 12 mA (typical).", 7 P2[7] (io) "GPIO Port 2 - Bit 7. Capable of sinking 7 mA (typical).", 8 P2[5] (io) "GPIO Port 2 - Bit 5. Capable of sinking 7 mA (typical).", 9 P2[3] (io) "GPIO Port 2 - Bit 3. Capable of sinking 7 mA (typical).", 10 P2[1] (io) "GPIO Port 2 - Bit 1. Capable of sinking 7 mA (typical).", 11 P1[7] (io) "GPIO Port 1 - Bit 7. Capable of sinking 7 mA (typical).", 12 P1[5] (io) "GPIO Port 1 - Bit 5. Capable of sinking 7 mA (typical).", 13 P1[3] (io) "GPIO Port 1 - Bit 3. Capable of sinking 7 mA (typical).", 14 P1[1] (io) "GPIO Port 1 - Bit 1. Capable of sinking 7 mA (typical).", 15 P0[7] (io) "GPIO port 0 - Bit 7. Capable of sinking 7 mA (typical)", 16 P0[5] (io) "GPIO port 0 - Bit 5. Capable of sinking 7 mA (typical)", 17 P0[3] (io) "GPIO port 0 - Bit 3. Capable of sinking 7 mA (typical)", 18 P0[1] (io) "GPIO port 0 - Bit 1. Capable of sinking 7 mA (typical)", 19 VPP (power) "Programming voltage supply, ground during operation", 20 VSS (power) "Ground", 21 XTALIN (in) "6-MHz ceramic resonator or external clock input", 22 XTALOUT (out) "6-MHz ceramic resonator", 23 P0[0] (io) "GPIO port 0 - Bit 0. Capable of sinking 7 mA (typical)", 24 P0[2] (io) "GPIO port 0 - Bit 2. Capable of sinking 7 mA (typical)", 25 P0[4] (io) "GPIO port 0 - Bit 4. Capable of sinking 7 mA (typical)", 26 P0[6] (io) "GPIO port 0 - Bit 6. Capable of sinking 7 mA (typical)", 27 P1[0] (io) "GPIO Port 1 - Bit 0. Capable of sinking 7 mA (typical).", 28 P1[2] (io) "GPIO Port 1 - Bit 2. Capable of sinking 7 mA (typical).", 29 P1[4] (io) "GPIO Port 1 - Bit 4. Capable of sinking 7 mA (typical).", 30 P1[6] (io) "GPIO Port 1 - Bit 6. Capable of sinking 7 mA (typical).", 31 P2[0] (io) "GPIO Port 2 - Bit 0. Capable of sinking 7 mA (typical).", 32 P2[2] (io) "GPIO Port 2 - Bit 2. Capable of sinking 7 mA (typical).", 33 P2[4] (io) "GPIO Port 2 - Bit 4. Capable of sinking 7 mA (typical).", 34 P2[6] (io) "GPIO Port 2 - Bit 6. Capable of sinking 7 mA (typical).", 35 P3[0] (io) "GPIO Port 3 - Bit 0. Capable of sinking 12 mA (typical).", 36 P3[2] (io) "GPIO Port 3 - Bit 2. Capable of sinking 12 mA (typical).", 37 P3[4] (io) "GPIO Port 3 - Bit 4. Capable of sinking 12 mA (typical).", 38 P3[6] (io) "GPIO Port 3 - Bit 6. Capable of sinking 12 mA (typical).", 39 VSS (power) "Ground", 40 VCC (power) "Voltage supply"

## CY7C63513-PVC
designator U?
Low-Speed USB Microcontroller, 8KB EPROM, 48-Pin SSOP, Commercial Grade
footprint O48_N (SOP, 48-Leads, Body 15.9x7.5mm, Pitch 0.635mm, IPC Medium Density)
footprint O48_L (SOP, 48-Leads, Body 15.9x7.5mm, Pitch 0.635mm, IPC High Density)
footprint O48_M (SOP, 48-Leads, Body 15.9x7.5mm, Pitch 0.635mm, IPC Low Density)
pins: 1 D+ (io) "USB differential data; PS/2 clock and data signals", 2 D- (io) "USB differential data; PS/2 clock and data signals", 3 P3[7] (io) "GPIO Port 3 - Bit 7. Capable of sinking 12 mA (typical).", 4 P3[5] (io) "GPIO Port 3 - Bit 5. Capable of sinking 12 mA (typical).", 5 P3[3] (io) "GPIO Port 3 - Bit 3. Capable of sinking 12 mA (typical).", 6 P3[1] (io) "GPIO Port 3 - Bit 1. Capable of sinking 12 mA (typical).", 7 P2[7] (io) "GPIO Port 2 - Bit 7. Capable of sinking 7 mA (typical).", 8 P2[5] (io) "GPIO Port 2 - Bit 5. Capable of sinking 7 mA (typical).", 9 P2[3] (io) "GPIO Port 2 - Bit 3. Capable of sinking 7 mA (typical).", 10 P2[1] (io) "GPIO Port 2 - Bit 1. Capable of sinking 7 mA (typical).", 11 P1[7] (io) "GPIO Port 1 - Bit 7. Capable of sinking 7 mA (typical).", 12 P1[5] (io) "GPIO Port 1 - Bit 5. Capable of sinking 7 mA (typical).", 13 P1[3] (io) "GPIO Port 1 - Bit 3. Capable of sinking 7 mA (typical).", 14 P1[1] (io) "GPIO Port 1 - Bit 1. Capable of sinking 7 mA (typical).", 15 DAC[7] (io) "DAC I/O Port - Bit 7, with programmable current sink outputs. Has a programmable sink current range of 0.2 to 1.0 mA typical.", 16 DAC[5] (io) "DAC I/O Port - Bit 5, with programmable current sink outputs. Has a programmable sink current range of 0.2 to 1.0 mA typical.", 17 P0[7] (io) "GPIO port 0 - Bit 7. Capable of sinking 7 mA (typical)", 18 P0[5] (io) "GPIO port 0 - Bit 5. Capable of sinking 7 mA (typical)", 19 P0[3] (io) "GPIO port 0 - Bit 3. Capable of sinking 7 mA (typical)", 20 P0[1] (io) "GPIO port 0 - Bit 1. Capable of sinking 7 mA (typical)", 21 DAC[3] (io) "DAC I/O Port - Bit 3, with programmable current sink outputs. Has a programmable sink current range of 0.2 to 1.0 mA typical.", 22 DAC[1] (io) "DAC I/O Port - Bit 1, with programmable current sink outputs. Has a programmable range of 3.2 to 16 mA typical.", 23 VPP (power) "Programming voltage supply, ground during operation", 24 VSS (power) "Ground", 25 XTALIN (in) "6-MHz ceramic resonator or external clock input", 26 XTALOUT (out) "6-MHz ceramic resonator", 27 DAC[0] (io) "DAC I/O Port - Bit 0, with programmable current sink outputs. Has a programmable range of 3.2 to 16 mA typical.", 28 DAC[2] (io) "DAC I/O Port - Bit 2, with programmable current sink outputs. Has a programmable sink current range of 0.2 to 1.0 mA typical.", 29 P0[0] (io) "GPIO port 0 - Bit 0. Capable of sinking 7 mA (typical)", 30 P0[2] (io) "GPIO port 0 - Bit 2. Capable of sinking 7 mA (typical)", 31 P0[4] (io) "GPIO port 0 - Bit 4. Capable of sinking 7 mA (typical)", 32 P0[6] (io) "GPIO port 0 - Bit 6. Capable of sinking 7 mA (typical)", 33 DAC[4] (io) "DAC I/O Port - Bit 4, with programmable current sink outputs. Has a programmable sink current range of 0.2 to 1.0 mA typical.", 34 DAC[6] (io) "DAC I/O Port - Bit 6, with programmable current sink outputs. Has a programmable sink current range of 0.2 to 1.0 mA typical.", 35 P1[0] (io) "GPIO Port 1 - Bit 0. Capable of sinking 7 mA (typical).", 36 P1[2] (io) "GPIO Port 1 - Bit 2. Capable of sinking 7 mA (typical).", 37 P1[4] (io) "GPIO Port 1 - Bit 4. Capable of sinking 7 mA (typical).", 38 P1[6] (io) "GPIO Port 1 - Bit 6. Capable of sinking 7 mA (typical).", 39 P2[0] (io) "GPIO Port 2 - Bit 0. Capable of sinking 7 mA (typical).", 40 P2[2] (io) "GPIO Port 2 - Bit 2. Capable of sinking 7 mA (typical).", 41 P2[4] (io) "GPIO Port 2 - Bit 4. Capable of sinking 7 mA (typical).", 42 P2[6] (io) "GPIO Port 2 - Bit 6. Capable of sinking 7 mA (typical).", 43 P3[0] (io) "GPIO Port 3 - Bit 0. Capable of sinking 12 mA (typical).", 44 P3[2] (io) "GPIO Port 3 - Bit 2. Capable of sinking 12 mA (typical).", 45 P3[4] (io) "GPIO Port 3 - Bit 4. Capable of sinking 12 mA (typical).", 46 P3[6] (io) "GPIO Port 3 - Bit 6. Capable of sinking 12 mA (typical).", 47 VSS (power) "Ground", 48 VCC (power) "Voltage supply"

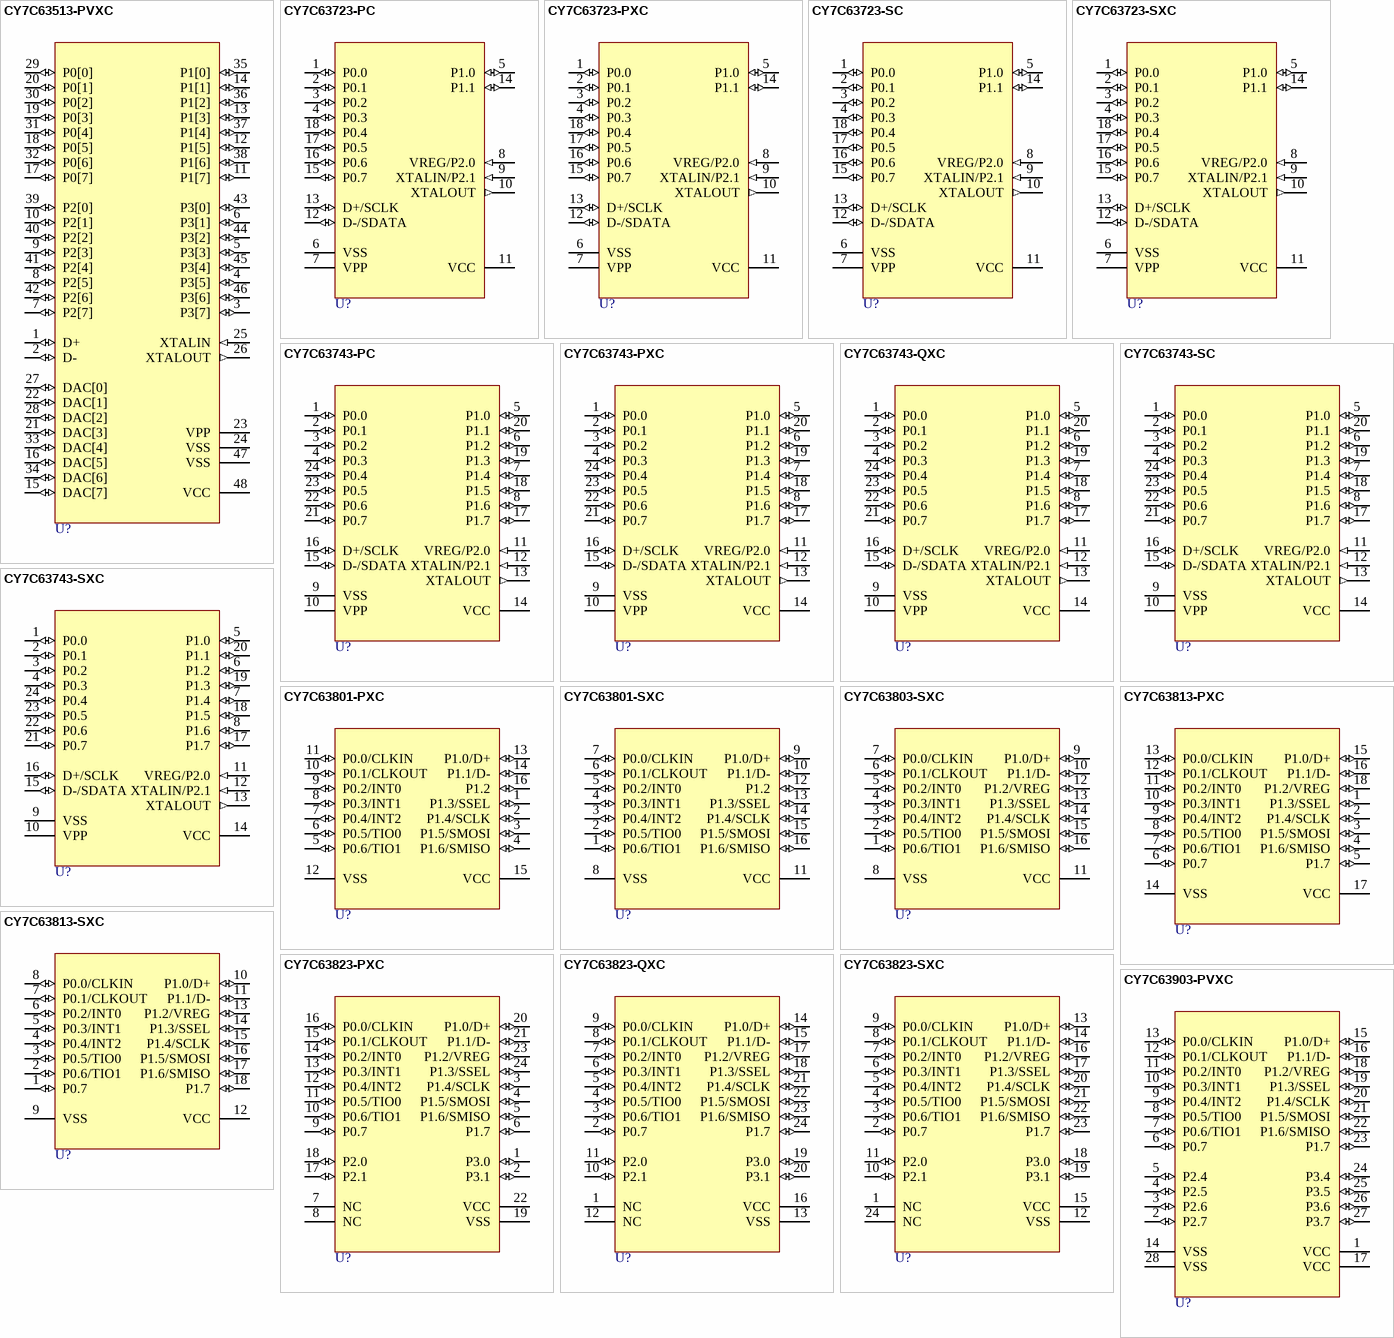
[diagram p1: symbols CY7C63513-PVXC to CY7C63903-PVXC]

## CY7C63513-PVXC
designator U?
Low-Speed USB Microcontroller, 8KB EPROM, 48-Pin SSOP, Commercial Grade, Pb-free
footprint SP48_N (SOP, 48-Leads, Body 15.9x7.5mm, Pitch 0.635mm, IPC Medium Density)
footprint SP48_L (SOP, 48-Leads, Body 15.9x7.5mm, Pitch 0.635mm, IPC High Density)
footprint SP48_M (SOP, 48-Leads, Body 15.9x7.5mm, Pitch 0.635mm, IPC Low Density)
pins: 1 D+ (io) "USB differential data; PS/2 clock and data signals", 2 D- (io) "USB differential data; PS/2 clock and data signals", 3 P3[7] (io) "GPIO Port 3 - Bit 7. Capable of sinking 12 mA (typical).", 4 P3[5] (io) "GPIO Port 3 - Bit 5. Capable of sinking 12 mA (typical).", 5 P3[3] (io) "GPIO Port 3 - Bit 3. Capable of sinking 12 mA (typical).", 6 P3[1] (io) "GPIO Port 3 - Bit 1. Capable of sinking 12 mA (typical).", 7 P2[7] (io) "GPIO Port 2 - Bit 7. Capable of sinking 7 mA (typical).", 8 P2[5] (io) "GPIO Port 2 - Bit 5. Capable of sinking 7 mA (typical).", 9 P2[3] (io) "GPIO Port 2 - Bit 3. Capable of sinking 7 mA (typical).", 10 P2[1] (io) "GPIO Port 2 - Bit 1. Capable of sinking 7 mA (typical).", 11 P1[7] (io) "GPIO Port 1 - Bit 7. Capable of sinking 7 mA (typical).", 12 P1[5] (io) "GPIO Port 1 - Bit 5. Capable of sinking 7 mA (typical).", 13 P1[3] (io) "GPIO Port 1 - Bit 3. Capable of sinking 7 mA (typical).", 14 P1[1] (io) "GPIO Port 1 - Bit 1. Capable of sinking 7 mA (typical).", 15 DAC[7] (io) "DAC I/O Port - Bit 7, with programmable current sink outputs. Has a programmable sink current range of 0.2 to 1.0 mA typical.", 16 DAC[5] (io) "DAC I/O Port - Bit 5, with programmable current sink outputs. Has a programmable sink current range of 0.2 to 1.0 mA typical.", 17 P0[7] (io) "GPIO port 0 - Bit 7. Capable of sinking 7 mA (typical)", 18 P0[5] (io) "GPIO port 0 - Bit 5. Capable of sinking 7 mA (typical)", 19 P0[3] (io) "GPIO port 0 - Bit 3. Capable of sinking 7 mA (typical)", 20 P0[1] (io) "GPIO port 0 - Bit 1. Capable of sinking 7 mA (typical)", 21 DAC[3] (io) "DAC I/O Port - Bit 3, with programmable current sink outputs. Has a programmable sink current range of 0.2 to 1.0 mA typical.", 22 DAC[1] (io) "DAC I/O Port - Bit 1, with programmable current sink outputs. Has a programmable range of 3.2 to 16 mA typical.", 23 VPP (power) "Programming voltage supply, ground during operation", 24 VSS (power) "Ground", 25 XTALIN (in) "6-MHz ceramic resonator or external clock input", 26 XTALOUT (out) "6-MHz ceramic resonator", 27 DAC[0] (io) "DAC I/O Port - Bit 0, with programmable current sink outputs. Has a programmable range of 3.2 to 16 mA typical.", 28 DAC[2] (io) "DAC I/O Port - Bit 2, with programmable current sink outputs. Has a programmable sink current range of 0.2 to 1.0 mA typical.", 29 P0[0] (io) "GPIO port 0 - Bit 0. Capable of sinking 7 mA (typical)", 30 P0[2] (io) "GPIO port 0 - Bit 2. Capable of sinking 7 mA (typical)", 31 P0[4] (io) "GPIO port 0 - Bit 4. Capable of sinking 7 mA (typical)", 32 P0[6] (io) "GPIO port 0 - Bit 6. Capable of sinking 7 mA (typical)", 33 DAC[4] (io) "DAC I/O Port - Bit 4, with programmable current sink outputs. Has a programmable sink current range of 0.2 to 1.0 mA typical.", 34 DAC[6] (io) "DAC I/O Port - Bit 6, with programmable current sink outputs. Has a programmable sink current range of 0.2 to 1.0 mA typical.", 35 P1[0] (io) "GPIO Port 1 - Bit 0. Capable of sinking 7 mA (typical).", 36 P1[2] (io) "GPIO Port 1 - Bit 2. Capable of sinking 7 mA (typical).", 37 P1[4] (io) "GPIO Port 1 - Bit 4. Capable of sinking 7 mA (typical).", 38 P1[6] (io) "GPIO Port 1 - Bit 6. Capable of sinking 7 mA (typical).", 39 P2[0] (io) "GPIO Port 2 - Bit 0. Capable of sinking 7 mA (typical).", 40 P2[2] (io) "GPIO Port 2 - Bit 2. Capable of sinking 7 mA (typical).", 41 P2[4] (io) "GPIO Port 2 - Bit 4. Capable of sinking 7 mA (typical).", 42 P2[6] (io) "GPIO Port 2 - Bit 6. Capable of sinking 7 mA (typical).", 43 P3[0] (io) "GPIO Port 3 - Bit 0. Capable of sinking 12 mA (typical).", 44 P3[2] (io) "GPIO Port 3 - Bit 2. Capable of sinking 12 mA (typical).", 45 P3[4] (io) "GPIO Port 3 - Bit 4. Capable of sinking 12 mA (typical).", 46 P3[6] (io) "GPIO Port 3 - Bit 6. Capable of sinking 12 mA (typical).", 47 VSS (power) "Ground", 48 VCC (power) "Voltage supply"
